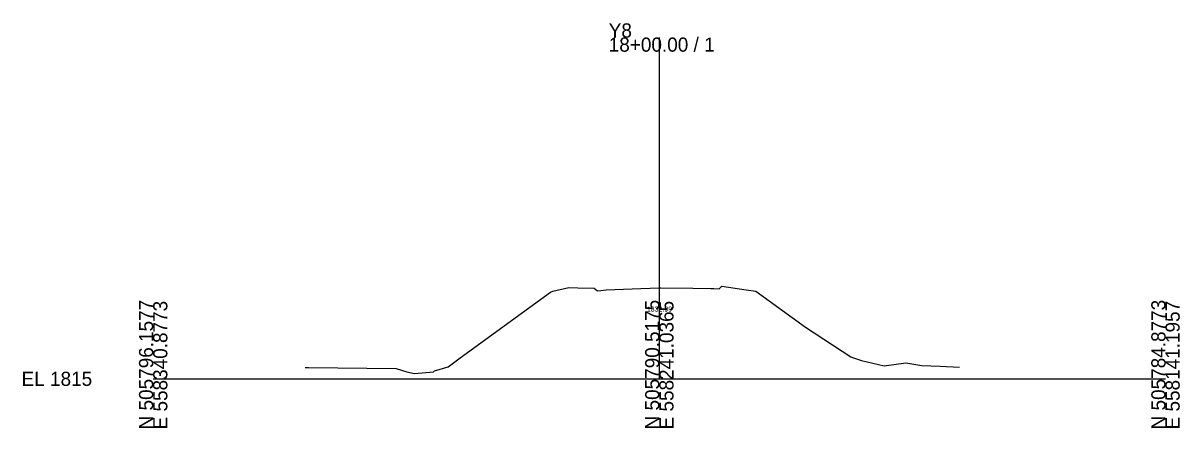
# Model space of a CAD drawing. Extents: x -26 to 203, y -10 to 8070.
# Drawn here: x -25.7 to 202.8, y 7990.3 to 8070.3 of the extents above; entities that cross this region are included whole.
import ezdxf

# ---------------------------------------------------------------- set-up
doc = ezdxf.new("R2010")
doc.units = 0
for name, color, linetype in [('Default', 7, 'Continuous'), ('Exist Cross Section Cell', 7, 'Continuous'), ('Exist XS Center Line Elevation Label', 7, 'Continuous'), ('Exist XS Ground Line', 7, 'Continuous')]:
    doc.layers.add(name, color=color, linetype=linetype)

msp = doc.modelspace()

# ---------------------------------------------------------------- linework, layer by layer
at = {"layer": 'Exist Cross Section Cell'}
for p, q in [((100, 8000), (100, 8067.43)), ((0, 8000), (100, 8000)), ((100, 8000), (200, 8000))]:
    msp.add_line(p, q, dxfattribs=at)
at = {"layer": 'Exist XS Ground Line'}
for p, q in [((60.63, 8004.13), (78.5, 8017.14)), ((78.5, 8017.14), (78.99, 8017.29)), ((78.99, 8017.29), (82.09, 8018.03)), ((82.09, 8018.03), (83.9, 8017.99)), ((83.9, 8017.99), (87.1, 8017.94)), ((87.1, 8017.94), (87.76, 8017.4)), ((87.76, 8017.4), (88.42, 8017.42)), ((88.42, 8017.42), (89.52, 8017.55)), ((89.52, 8017.55), (96.34, 8017.86)), ((96.34, 8017.86), (100, 8017.99)), ((100, 8017.99), (100.31, 8018)), ((100.31, 8018), (106.64, 8017.92)), ((106.64, 8017.92), (110.2, 8017.83)), ((110.2, 8017.83), (110.76, 8017.82)), ((110.76, 8017.82), (111.82, 8017.81)), ((111.82, 8017.81), (112.38, 8018.29)), ((112.38, 8018.29), (117.15, 8017.57)), ((117.15, 8017.57), (119.06, 8017.31)), ((119.06, 8017.31), (128.86, 8010.23)), ((128.86, 8010.23), (137.81, 8004.34)), ((58.26, 8002.38), (60.63, 8004.13)), ((137.81, 8004.34), (138.35, 8004.16)), ((138.35, 8004.16), (139.96, 8003.6)), ((139.96, 8003.6), (144.45, 8002.56)), ((30, 8002.25), (30.69, 8002.23)), ((30.69, 8002.23), (47.98, 8002.01)), ((47.98, 8002.01), (50.1, 8001.4)), ((50.1, 8001.4), (51.64, 8001.02)), ((51.64, 8001.02), (55.38, 8001.37)), ((55.38, 8001.37), (55.6, 8001.56)), ((55.6, 8001.56), (58.26, 8002.38)), ((144.45, 8002.56), (148.68, 8003.14)), ((148.68, 8003.14), (151.86, 8002.64)), ((151.86, 8002.64), (155.48, 8002.5)), ((155.48, 8002.5), (159.28, 8002.27))]:
    msp.add_line(p, q, dxfattribs=at)

# ---------------------------------------------------------------- texts
at = {"layer": 'Default'}
msp.add_text('-', height=0.0001, dxfattribs=at).set_placement((0, 8000))
at = {"layer": 'Exist Cross Section Cell'}
for s, p in [('Y8', (90, 8067.43)), ('18+00.00 / 1', (90, 8064.63)), ('EL 1815', (-26, 7998.6))]:
    msp.add_text(s, height=2.8, dxfattribs=at).set_placement(p)
for s, p in [('N 505796.1577', (0, 7990)), ('E 558340.8773', (2.8, 7990)), ('N 505790.5175', (100, 7990)), ('E 558241.0365', (102.8, 7990)), ('N 505784.8773', (200, 7990)), ('E 558141.1957', (202.8, 7990))]:
    msp.add_text(s, height=2.8, rotation=90, dxfattribs=at).set_placement(p)
at = {"layer": 'Exist XS Center Line Elevation Label'}
msp.add_text('1832.99', height=1, dxfattribs=at).set_placement((97.53, 8013.28))

doc.saveas('drawing.dxf')
